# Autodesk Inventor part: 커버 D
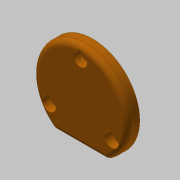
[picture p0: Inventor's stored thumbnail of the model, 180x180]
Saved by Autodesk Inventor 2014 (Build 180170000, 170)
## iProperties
Created: 2020-04
Part Number: 커버 D
Material: 알루미늄 6061
Document SubType Name: Modeling
Designer: mduedu
Density: 2.71 g/cm^3
Mass: 32.8423 g
Surface Area: 61.5912 cm^2
Volume: 12.1189 cm^3
Appearance: 주황색
Author: mduedu
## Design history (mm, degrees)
sketch "스케치1"
  geometry: C1 r 26 at (0, 0); 1 further point
  constraints: 1 centre point, 1 coincident
  dimensions: "d0" = 52 diameter of C1
extrude "돌출1" new body sketch "스케치1" distance "d1" = 7; taper "d2" = 0 deg
sketch "스케치2"
  geometry: L1 (-14.62, -21.5)-(14.62, -21.5); A1 r 26 centre (0, 0) between (-14.62, -21.5) and (14.62, -21.5) reference; 1 further point
  constraints: 2 end point, 2 point on circle, 1 horizontal
  dimensions: "d3" = 21.5 distance from line of L1 point (0, 0)
extrude "돌출2" cut sketch "스케치2" stored distance "d4" = 7; taper "d5" = 0 deg
fillet "모깎기1" dims "d6" = 3
fillet "모깎기2" dims "d7" = 3
sketch "스케치3" dims "d8" = 40
  geometry: 3 further points
  constraints: 2 vertical alignment, 1 coincident, 2 other
hole "구멍1" sketch "스케치3" at (0, 20) diameter "d9" = 4.5; stored, may be unused: countersink angle "d13" = 90 deg, drill point angle "d15" = 118 deg; dims "d10" = 6, "d11" = 8, "d12" = 4.4, "d14" = 8
sketch "스케치4"
  geometry: C1 r 14 at (0, 0); 1 further point
  constraints: 1 centre point, 1 coincident
  dimensions: "d19" = 28 diameter of C1
extrude "돌출3" join sketch "스케치4" distance "d20" = 4; taper "d21" = 0 deg
sketch "스케치5"
  geometry: C1 r 12 at (0, 0); 1 further point
  constraints: 1 centre point, 1 coincident
  dimensions: "d22" = 24 diameter of C1
extrude "돌출4" cut sketch "스케치5" distance "d23" = 8; taper "d24" = 0 deg
fillet "모깎기3" dims "d25" = 3
chamfer "모따기1" distance "d26" = 0.5; stored, may be unused: second distance "d27" = 2, angle "d28" = 45 deg
node "솔리드1"
pattern_circular "원형 패턴1" dims angle "d17" = 360 deg
node "투영된 루프1"
